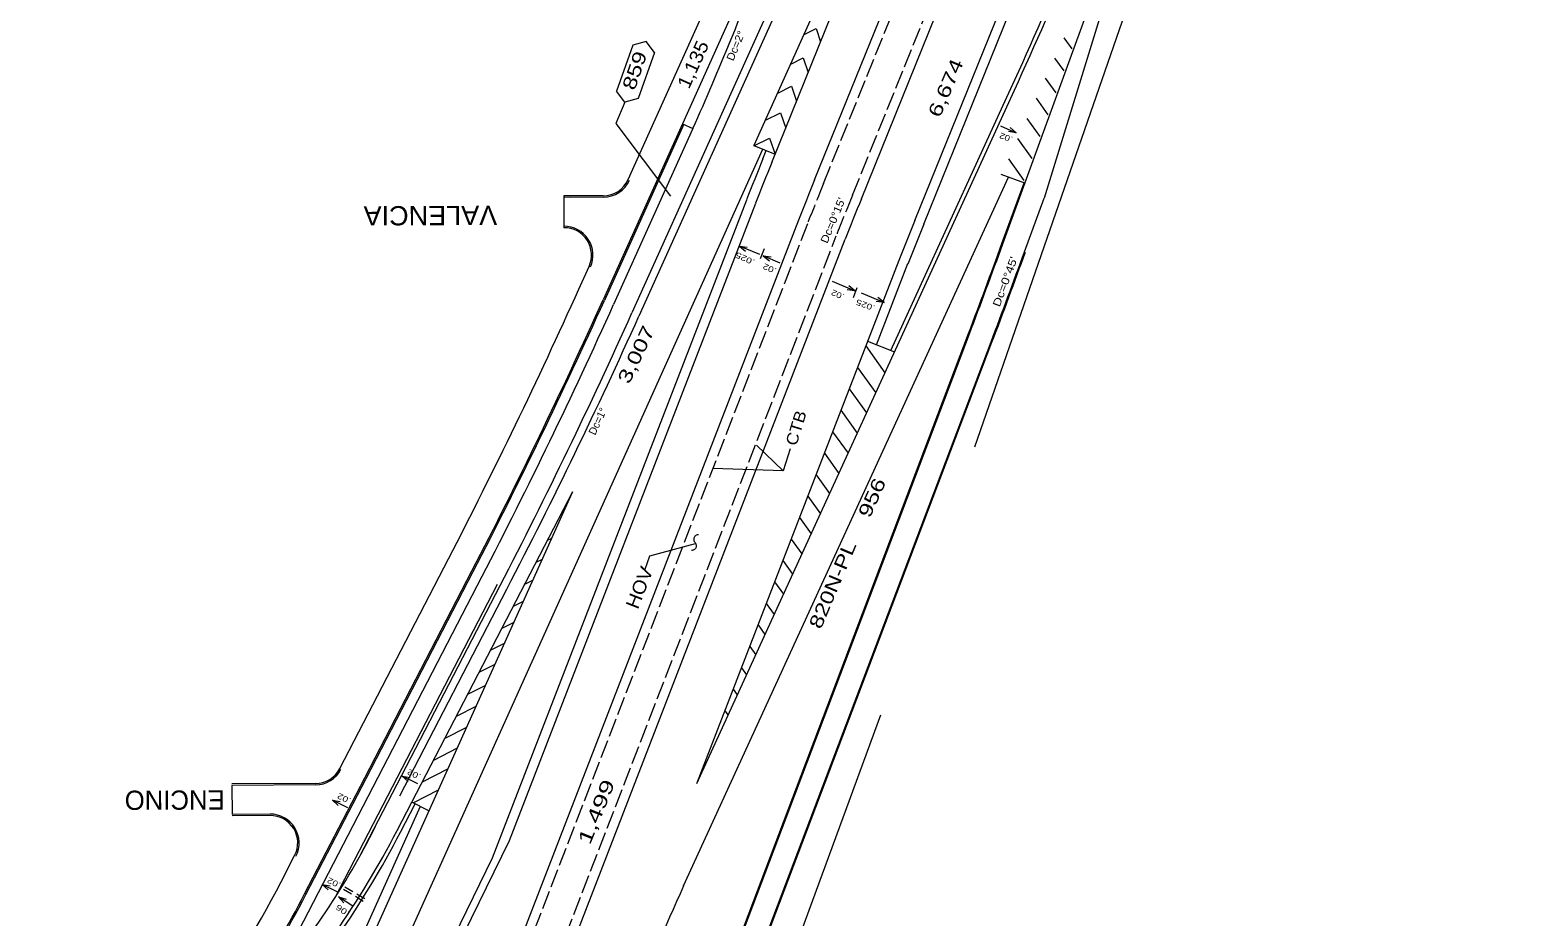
# Model space of a CAD drawing. Extents: x 2354993 to 2372084, y 6966390 to 6990057.
# Drawn here: x 2364884 to 2366452, y 6981393 to 6982315 of the extents above; entities that cross this region are included whole.
import ezdxf

# ---------------------------------------------------------------- set-up
doc = ezdxf.new("R2010")
doc.units = 0
doc.header["$LTSCALE"] = 3.2
doc.linetypes.add('LONG_DASHED', pattern=[7.5, 6, -1.5])
doc.linetypes.add('MEDIUM_DASHED', pattern=[4.5, 3, -1.5])
for name, color, linetype, lineweight in [('10', 7, 'Continuous', 13), ('12', 7, 'Continuous', 13), ('13', 7, 'Continuous', 13), ('17', 7, 'Continuous', 13), ('19', 7, 'Continuous', 13), ('25', 7, 'Continuous', 13), ('4', 7, 'Continuous', 13), ('5', 7, 'Continuous', 13), ('9', 7, 'Continuous', 13)]:
    doc.layers.add(name, color=color, linetype=linetype, lineweight=lineweight)

msp = doc.modelspace()

# ---------------------------------------------------------------- linework, layer by layer
at = {"layer": '10'}
msp.add_arc((2358740.096, 6984698.511), 7640.437, 339.24044, 339.9908, dxfattribs=at)
at = {"layer": '12', "linetype": 'MEDIUM_DASHED'}
for p, q in [((2365230.832, 6981409.397), (2365208.441, 6981422.614)), ((2365232.368, 6981411.974), (2365209.977, 6981425.191))]:
    msp.add_line(p, q, dxfattribs=at)
at = {"layer": '13'}
msp.add_line((2365510.907, 6982298.979), (2365493.918, 6982251.353), dxfattribs=at)
for points in [[(2365533.695, 6982291.446), (2365524.87, 6982302.789), (2365510.907, 6982298.979)], [(2365533.695, 6982291.446), (2365516.704, 6982243.818), (2365502.742, 6982240.009), (2365493.918, 6982251.353)], [(2365502.742, 6982240.009), (2365493.365, 6982217.721), (2365550.177, 6982142.129)], [(2365523.937, 6981754.741), (2365528.75, 6981768.443), (2365576.386, 6981781.284)], [(2365579.387, 6981790.427), (2365577.948, 6981790.249), (2365576.978, 6981789.862), (2365576.231, 6981789.374), (2365575.638, 6981788.818), (2365575.169, 6981788.207), (2365574.811, 6981787.545), (2365574.556, 6981786.837), (2365574.413, 6981786.079), (2365574.394, 6981785.266), (2365574.527, 6981784.384), (2365574.886, 6981783.403), (2365575.186, 6981782.875), (2365575.712, 6981782.213), (2365576.236, 6981781.547), (2365576.536, 6981781.022), (2365576.679, 6981780.703), (2365576.895, 6981780.039), (2365576.989, 6981779.558), (2365577.029, 6981779.157), (2365577.009, 6981778.346), (2365576.866, 6981777.588), (2365576.613, 6981776.88), (2365576.253, 6981776.219), (2365575.783, 6981775.607), (2365575.192, 6981775.05), (2365574.444, 6981774.563), (2365573.807, 6981774.281), (2365573.474, 6981774.175), (2365572.881, 6981774.048), (2365572.037, 6981773.997)]]:
    msp.add_lwpolyline(points, dxfattribs=at)
at = {"layer": '19'}
for p, q in [((2365893.323, 6982215.361), (2365909.789, 6982208.072)), ((2365909.789, 6982208.072), (2365901.562, 6982209.227)), ((2365909.789, 6982208.072), (2365903.401, 6982213.388)), ((2365621.858, 6982090.33), (2365628.356, 6982085.156)), ((2365621.858, 6982090.33), (2365630.112, 6982089.355)), ((2365642.949, 6982081.536), (2365621.858, 6982090.33)), ((2365647.522, 6982087.307), (2365643.569, 6982077.208)), ((2365646.512, 6982080.169), (2365653.01, 6982074.995)), ((2365646.512, 6982080.169), (2365654.765, 6982079.194)), ((2365664.327, 6982072.741), (2365646.512, 6982080.169)), ((2365742.024, 6982043.676), (2365733.782, 6982044.741)), ((2365740.592, 6982036.979), (2365744.357, 6982047.15)), ((2365772.228, 6982031.661), (2365763.985, 6982032.726)), ((2365271.369, 6981539.541), (2365277.566, 6981534.01)), ((2365271.369, 6981539.541), (2365279.555, 6981538.104)), ((2365287.574, 6981531.688), (2365271.369, 6981539.541)), ((2365198.647, 6981514.536), (2365204.844, 6981509.005)), ((2365198.647, 6981514.536), (2365206.833, 6981513.099)), ((2365214.852, 6981506.683), (2365198.647, 6981514.536)), ((2365188.077, 6981426.882), (2365194.274, 6981421.351)), ((2365188.077, 6981426.882), (2365196.263, 6981425.445)), ((2365204.282, 6981419.029), (2365188.077, 6981426.882)), ((2365205.079, 6981414.245), (2365210.455, 6981407.913)), ((2365205.079, 6981414.245), (2365212.989, 6981411.694)), ((2365220.047, 6981404.234), (2365205.079, 6981414.245))]:
    msp.add_line(p, q, dxfattribs=at)
for points in [[(2365718.336, 6982053.856), (2365742.024, 6982043.676), (2365735.583, 6982048.92)], [(2365748.54, 6982041.841), (2365772.228, 6982031.661), (2365765.786, 6982036.905)]]:
    msp.add_lwpolyline(points, dxfattribs=at)
at = {"layer": '25'}
for p, q in [((2365858.107, 6982773.741), (2365517.469, 6982017.581)), ((2365655.565, 6982177.229), (2365892.178, 6982761.724)), ((2365879.26, 6982733.049), (2365636.764, 6982194.747)), ((2365506.33, 6982159.631), (2365756.042, 6982713.951)), ((2365700.058, 6982159.218), (2365878.037, 6982598.874)), ((2365748.722, 6982139.518), (2365926.701, 6982579.174)), ((2365562.571, 6982217.52), (2365480.087, 6982034.421)), ((2365563.939, 6982216.904), (2365481.455, 6982033.805)), ((2365636.764, 6982194.747), (2365659.01, 6982185.741)), ((2365480.379, 6982142.597), (2365439.311, 6982142.392)), ((2365439.311, 6982142.392), (2365439.474, 6982109.426)), ((2365480.387, 6982141.097), (2365439.318, 6982140.892)), ((2365480.387, 6982141.097), (2365446.259, 6982140.927)), ((2365638.459, 6982134.483), (2365382.326, 6981472.187)), ((2365683.228, 6982117.169), (2365358.55, 6981277.634)), ((2365407.217, 6981257.934), (2365731.885, 6982097.447)), ((2365455.01, 6982045.709), (2365465.601, 6982069.22)), ((2365667.481, 6981856.792), (2365594.184, 6981859.199)), ((2365029.335, 6980904.779), (2365448.587, 6981835.455)), ((2365281.153, 6981512.478), (2365448.571, 6981835.42)), ((2365206.278, 6981547.302), (2365319.371, 6981765.458)), ((2365232.324, 6981537.792), (2365343.797, 6981752.824)), ((2365233.656, 6981537.102), (2365345.129, 6981752.134)), ((2365268.724, 6981518.921), (2365380.197, 6981733.953)), ((2365169.806, 6981417.192), (2365232.324, 6981537.792)), ((2365171.138, 6981416.502), (2365233.656, 6981537.102)), ((2365265.914, 6981483.077), (2365281.155, 6981512.477)), ((2365299.063, 6981503.534), (2365281.153, 6981512.478)), ((2365382.326, 6981472.187), (2365167.295, 6981031.876)), ((2365145.393, 6981429.854), (2365159.418, 6981456.908))]:
    msp.add_line(p, q, dxfattribs=at)
at = {"layer": '25', "linetype": 'LONG_DASHED'}
for p, q in [((2365709.327, 6982155.466), (2365887.306, 6982595.122)), ((2365739.453, 6982143.27), (2365917.432, 6982582.926)), ((2365692.555, 6982113.562), (2365367.877, 6981274.027)), ((2365397.89, 6981261.541), (2365722.558, 6982101.054))]:
    msp.add_line(p, q, dxfattribs=at)
at = {"layer": '25'}
for points in [[(2365682.892, 6982484.609), (2365562.57, 6982217.518), (2365573.511, 6982212.589)], [(2365674.567, 6981879.694), (2365667.481, 6981856.792), (2365639.805, 6981883.28)]]:
    msp.add_lwpolyline(points, dxfattribs=at)
for centre, radius, start, end in [((2362974.286, 6983383.498), 2850.789, 335.74918, 339.77145), ((2371035.303, 6979999.424), 5803.828, 157.9611, 158.41195), ((2365480.237, 6982171.096), 28.5, 270.28559, 335.74925), ((2365480.237, 6982171.096), 30, 270.28559, 335.74925), ((2371035.304, 6979999.424), 5755.828, 157.9611, 158.41275), ((2371035.303, 6979999.424), 5703.328, 157.9611, 158.4163), ((2365439.616, 6982080.926), 30, 335.74944, 90.28559), ((2365439.616, 6982080.926), 28.5, 335.74944, 90.28533), ((2360293.486, 6984370.89), 5661.078, 332.59766, 335.74922), ((2360293.489, 6984370.897), 5688.578, 332.59784, 335.74923), ((2360293.489, 6984370.897), 5690.078, 332.59784, 335.74923), ((2360293.489, 6984370.896), 5729.578, 332.59784, 335.74923), ((2364406.014, 6981928.856), 968.58, 317.77096, 332.59746), ((2364129.385, 6981956.555), 1144.416, 323.97105, 332.59766), ((2364129.386, 6981956.557), 1171.916, 321.88117, 332.59727), ((2364129.386, 6981956.557), 1173.416, 326.58947, 332.59727)]:
    msp.add_arc(centre, radius, start, end, dxfattribs=at)
at = {"layer": '25', "linetype": 'LONG_DASHED'}
for centre, radius, end in [((2371035.304, 6979999.424), 5745.828, 158.41275), ((2371035.303, 6979999.424), 5713.328, 158.4163)]:
    msp.add_arc(centre, radius, 157.9611, end, dxfattribs=at)
at = {"layer": '4'}
for p, q in [((2365850.813, 6982777.027), (2365510.175, 6982020.867)), ((2365645.882, 6982190.639), (2365062.309, 6980895.203)), ((2365646.296, 6982180.981), (2365649.742, 6982189.493)), ((2365629.132, 6982138.09), (2365364.685, 6981454.295)), ((2365201.706, 6981413.541), (2365370.432, 6981739.016)), ((2365227.335, 6981456.463), (2365373.095, 6981737.635)), ((2365290.106, 6981508.007), (2365022.191, 6980913.275)), ((2365269.466, 6981481.236), (2365284.706, 6981510.636)), ((2365364.685, 6981454.295), (2365160.333, 6981035.852))]:
    msp.add_line(p, q, dxfattribs=at)
for points in [[(2365689.17, 6982310.318), (2365701.705, 6982316.447), (2365706.351, 6982302.686)], [(2365675.236, 6982279.386), (2365688.317, 6982285.782), (2365693.406, 6982270.708)], [(2365661.728, 6982249.402), (2365676.018, 6982256.389), (2365681.289, 6982240.776)], [(2365649.056, 6982221.271), (2365664.597, 6982228.87), (2365669.996, 6982212.879)], [(2365637.054, 6982194.628), (2365653.324, 6982202.583), (2365659.01, 6982185.741)]]:
    msp.add_lwpolyline(points, dxfattribs=at)
for centre, radius, start, end in [((2371035.303, 6979999.424), 5813.828, 157.9611, 158.41195), ((2360293.489, 6984370.896), 5721.578, 332.59784, 335.74923), ((2364406.014, 6981928.856), 972.58, 317.77096, 332.59746), ((2364530.202, 6981842.504), 796.823, 319.17372, 334.00023)]:
    msp.add_arc(centre, radius, start, end, dxfattribs=at)
at = {"layer": '5'}
for p, q in [((2365804.338, 6982117.004), (2365982.317, 6982556.66)), ((2365813.607, 6982113.252), (2365991.586, 6982552.908)), ((2365895.848, 6982092.73), (2366007.685, 6982399.844)), ((2366008.225, 6982366.256), (2365938.683, 6982140.218)), ((2366025.609, 6982341.071), (2365866.293, 6981881.435)), ((2365959.101, 6982306.746), (2365967.427, 6982295.137)), ((2365949.544, 6982285.755), (2365959.138, 6982272.376)), ((2365939.945, 6982264.82), (2365950.85, 6982249.615)), ((2365577.516, 6981531.942), (2365903.725, 6982243.407)), ((2365779.464, 6981981.99), (2365900.089, 6982245.074)), ((2365930.347, 6982243.886), (2365942.562, 6982226.854)), ((2365920.748, 6982222.952), (2365934.273, 6982204.093)), ((2365573.511, 6982212.589), (2365491.028, 6982029.491)), ((2365911.15, 6982202.018), (2365925.985, 6982181.332)), ((2365901.552, 6982181.083), (2365917.696, 6982158.571)), ((2365563.867, 6981425.395), (2365901.654, 6982162.111)), ((2365918.836, 6982155.854), (2365894.112, 6982164.858)), ((2365894.909, 6982093.072), (2365917.896, 6982156.197)), ((2365918.4, 6982084.517), (2365938.683, 6982140.218)), ((2365577.516, 6981531.942), (2365787.846, 6982075.805)), ((2365764.521, 6981987.769), (2365797.173, 6982072.198)), ((2365337.246, 6980620.046), (2365860.175, 6981999.596)), ((2365338.182, 6980619.691), (2365861.11, 6981999.242)), ((2365428.134, 6980789.285), (2365883.552, 6981990.735)), ((2365429.069, 6980788.933), (2365884.487, 6981990.381)), ((2365753.324, 6981986.538), (2365773.225, 6981958.787)), ((2365755.194, 6981991.376), (2365783.175, 6981980.555)), ((2365744.701, 6981964.243), (2365763.627, 6981937.852)), ((2365736.079, 6981941.948), (2365754.029, 6981916.918)), ((2365727.456, 6981919.652), (2365744.43, 6981895.984)), ((2365718.834, 6981897.357), (2365734.832, 6981875.05)), ((2365710.212, 6981875.062), (2365725.233, 6981854.115)), ((2365701.589, 6981852.766), (2365715.635, 6981833.181)), ((2365692.967, 6981830.471), (2365706.036, 6981812.247)), ((2365684.345, 6981808.176), (2365696.438, 6981791.312)), ((2365426.537, 6981786.508), (2365422.028, 6981784.22)), ((2365675.722, 6981785.88), (2365686.84, 6981770.378)), ((2365416.713, 6981764.7), (2365410.193, 6981761.391)), ((2365667.1, 6981763.585), (2365677.241, 6981749.444)), ((2365134.648, 6981323.301), (2365354.45, 6981747.299)), ((2365406.889, 6981742.892), (2365398.358, 6981738.562)), ((2365658.478, 6981741.29), (2365667.643, 6981728.51)), ((2365397.065, 6981721.084), (2365386.524, 6981715.733)), ((2365649.855, 6981718.994), (2365658.044, 6981707.575)), ((2365387.241, 6981699.275), (2365374.689, 6981692.905)), ((2365641.233, 6981696.699), (2365648.446, 6981686.641)), ((2365377.416, 6981677.467), (2365362.854, 6981670.076)), ((2365632.61, 6981674.403), (2365638.847, 6981665.707)), ((2365367.592, 6981655.659), (2365351.02, 6981647.248)), ((2365623.988, 6981652.108), (2365629.249, 6981644.772)), ((2365357.768, 6981633.851), (2365339.184, 6981624.418)), ((2365615.366, 6981629.813), (2365619.65, 6981623.838)), ((2365347.943, 6981612.041), (2365327.349, 6981601.588)), ((2365606.743, 6981607.517), (2365610.052, 6981602.904)), ((2365338.119, 6981590.233), (2365315.516, 6981578.76)), ((2365328.295, 6981568.425), (2365303.682, 6981555.931)), ((2365318.471, 6981546.617), (2365291.848, 6981533.103)), ((2365181.13, 6981531.919), (2365094.158, 6981531.449)), ((2365308.646, 6981524.808), (2365282.85, 6981511.713)), ((2365133.831, 6981500.056), (2365094.609, 6981499.661)), ((2365133.846, 6981498.556), (2365094.624, 6981498.161))]:
    msp.add_line(p, q, dxfattribs=at)
for points in [[(2365569.779, 6981058.596), (2365647.705, 6981272.931), (2365768.875, 6981603.207)], [(2365181.138, 6981530.419), (2365094.166, 6981529.949), (2365094.609, 6981499.661)]]:
    msp.add_lwpolyline(points, dxfattribs=at)
for centre, radius, start, end in [((2360717.318, 6984621.39), 5701.578, 335.3684, 338.5448), ((2360717.318, 6984621.39), 5705.578, 335.3684, 338.5448), ((2371035.303, 6979999.424), 5643.328, 157.9611, 158.4163), ((2371035.303, 6979999.424), 5633.328, 157.9611, 158.4163), ((2358740.096, 6984698.511), 7614.437, 339.24044, 339.9908), ((2358740.096, 6984698.511), 7615.437, 339.24044, 339.9908), ((2358740.096, 6984698.511), 7639.437, 339.24044, 339.9908), ((2360293.489, 6984370.895), 5700.578, 332.59784, 335.74923), ((2365180.976, 6981560.419), 28.5, 270.30961, 332.59757), ((2365180.976, 6981560.419), 30, 270.30961, 332.59757), ((2365134.133, 6981470.057), 30, 332.59791, 90.57645), ((2365134.133, 6981470.057), 28.5, 332.59791, 90.57645), ((2368160.706, 6980234.736), 2856.789, 155.3684, 158.22353)]:
    msp.add_arc(centre, radius, start, end, dxfattribs=at)
at = {"layer": '9'}
msp.add_arc((2360722.521, 6984327.136), 5729.573, 359.50797, 359.50797, dxfattribs=at)

# ---------------------------------------------------------------- texts
at = {"layer": '13'}
for s, height, rotation, width, p in [('1,135', 14, 65.613, 1.1, (2365569.427, 6982252.742)), ('859', 14, 70.956, 1.3, (2365512.911, 6982251.313)), ('6,674', 14, 66.706, 1.35, (2365830.244, 6982222.869)), ('VALENCIA', 20, 180.22, 1.05, (2365369.997, 6982132.27)), ('3,007', 14, 64.566, 1.35, (2365507.227, 6981946.071)), ('CTB', 12, 72.807, 1.15, (2365681.055, 6981881.919)), ('820N-PL', 14, 67.104, 1.3, (2365706.524, 6981691.388)), ('HOV', 14, 68.713, 1.1, (2365516.323, 6981712.085)), ('1,499', 14, 67.927, 1.5, (2365466.399, 6981467.254))]:
    msp.add_text(s, height=height, rotation=rotation, dxfattribs=dict(at, width=width)).set_placement(p)
msp.add_text('ENCINO', height=20, rotation=180.22, dxfattribs=at).set_placement((2365086.671, 6981524.823))
at = {"layer": '17'}
for s, rotation, width, p in [('Dc=2°', 67.07, 1.1, (2365615.408, 6982281.992)), ("Dc=0°15'", 67.442, 1.15, (2365713.216, 6982092.416))]:
    msp.add_text(s, height=8, rotation=rotation, dxfattribs=dict(at, width=width)).set_placement(p)
msp.add_text('Dc=1°', height=8, rotation=64.778, dxfattribs=at).set_placement((2365471.842, 6981893.21))
at = {"layer": '19'}
for s, height, rotation, width, p in [('.02', 6, 160.217, 1.25, (2365906.655, 6982203.656)), ('.025', 5.999, 155.55, 1.35, (2365638.563, 6982075.684)), ("Dc=0°45'", 8, 69.681, 1.25, (2365892.488, 6982026.499)), ('.02', 6, 155.855, 1.3, (2365661.167, 6982066.71)), ('.02', 5.999, 156.311, 1.25, (2365731.75, 6982039.784)), ('.025', 6, 159.683, 1.3, (2365763.478, 6982028.252)), ('956', 14, 65.763, 1.35, (2365757.424, 6981806.828)), ('.02', 6, 154.187, 1.3, (2365291.387, 6981540.937)), ('.02', 6, 154.187, 1.3, (2365218.665, 6981515.932)), ('.02', 6, 154.187, 1.3, (2365208.095, 6981428.278)), ('.06', 6, 146.266, 1.35, (2365217.3, 6981398.427))]:
    msp.add_text(s, height=height, rotation=rotation, dxfattribs=dict(at, width=width)).set_placement(p)

doc.saveas('drawing.dxf')
